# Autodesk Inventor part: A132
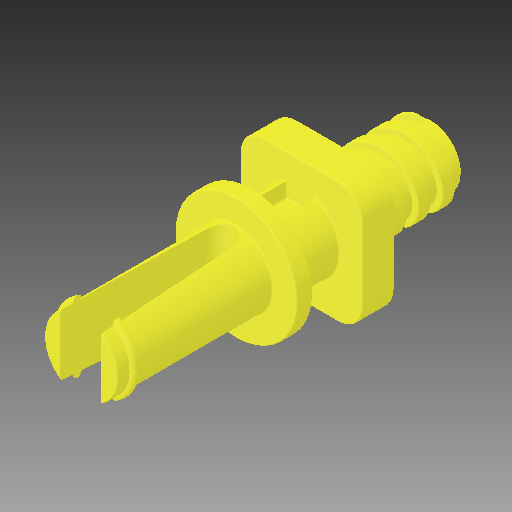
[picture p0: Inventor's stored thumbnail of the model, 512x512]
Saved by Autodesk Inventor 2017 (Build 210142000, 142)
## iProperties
Part Number: A132
Material: Générique
Document SubType Name: Modeling
Designer: ficho
Density: 1 g/cm^3
Appearance: Par défaut
Mass: 2.74312 g
Surface Area: 22.8498 cm^2
Volume: 2.74312 cm^3
Author: ficho
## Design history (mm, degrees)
feature "Solid1"
node "Solide1"
